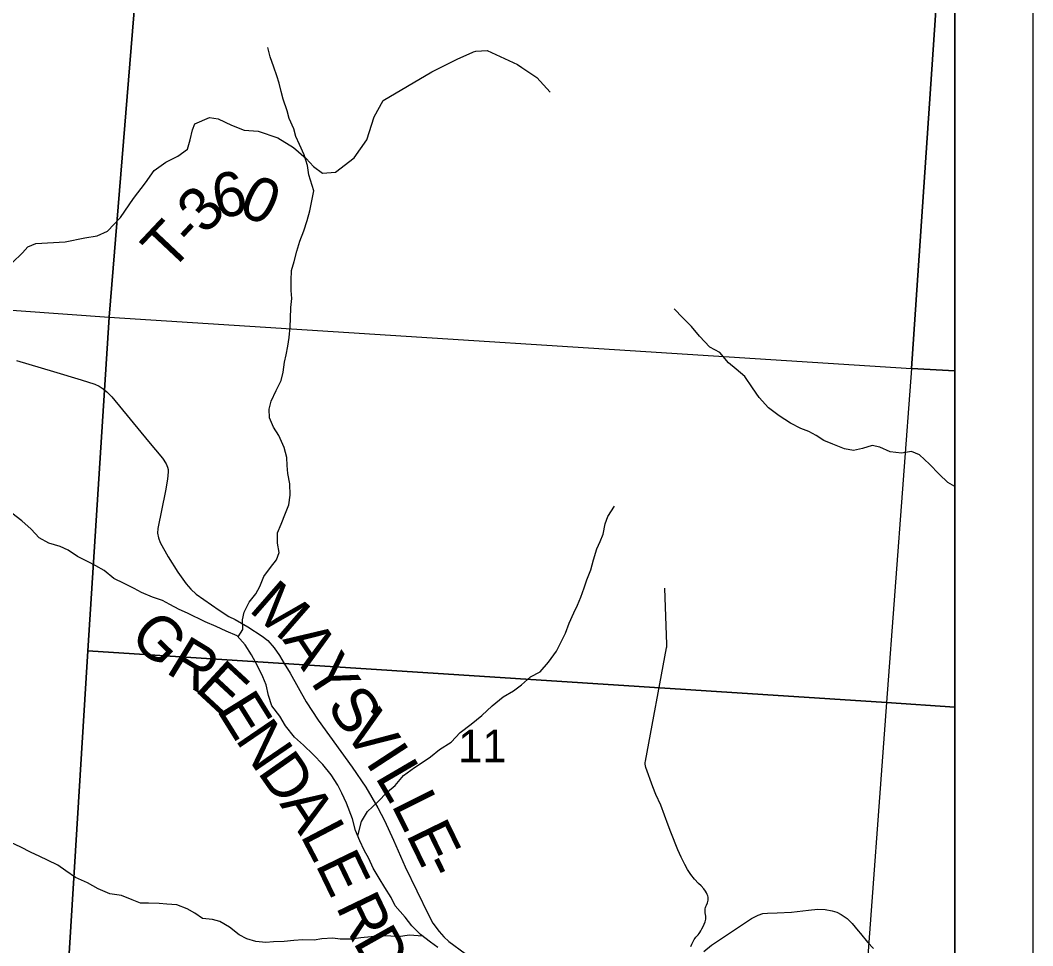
# Model space of a CAD drawing. Extents: x 39.8 to 73.8, y 13 to 35.
# Drawn here: x 47.463 to 48.763, y 32.203 to 33.391 of the extents above; entities that cross this region are included whole.
import ezdxf

# ---------------------------------------------------------------- set-up
doc = ezdxf.new("R2010")
doc.units = 0
for name, color, linetype in [('GM_X_Corporation', 7, 'Continuous'), ('GM_X_Minor_River', 7, 'Continuous'), ('GM_X_Section_Text', 7, 'Continuous'), ('GM_X_Township_Road', 7, 'Continuous'), ('GM_X_Township_Road_Text', 7, 'Continuous'), ('SH_Data', 7, 'Continuous')]:
    doc.layers.add(name, color=color, linetype=linetype)

msp = doc.modelspace()

# ---------------------------------------------------------------- linework, layer by layer
at = {"layer": 'GM_X_Corporation'}
msp.add_lwpolyline([(47.095, 27.8783), (47.5149, 27.8498), (47.5414, 27.8484), (48.663, 27.7809), (48.663, 33.865), (43.6158, 33.865)], dxfattribs=at)
for points in [[(47.647, 33.865), (46.6307, 33.865), (46.5718, 33.0824), (47.5774, 33.0099)], [(48.663, 33.7628), (48.663, 33.865), (47.647, 33.865), (47.5774, 33.0099), (48.6073, 32.9443)], [(48.663, 32.941), (48.663, 33.7628), (48.6073, 32.9443)], [(47.5774, 33.0099), (47.5501, 32.582), (47.5261, 32.1933), (47.514, 31.9975), (46.4973, 32.0662), (46.5718, 33.0824)], [(47.5774, 33.0099), (48.6073, 32.9443), (48.5754, 32.5153), (47.5501, 32.582)], [(48.663, 32.5097), (48.663, 32.941), (48.6073, 32.9443), (48.5754, 32.5153)], [(47.5501, 32.582), (48.5754, 32.5153), (48.5476, 32.1383), (47.5261, 32.1933)], [(48.663, 32.1321), (48.663, 32.5097), (48.5754, 32.5153), (48.5476, 32.1383)]]:
    msp.add_lwpolyline(points, close=True, dxfattribs=at)
at = {"layer": 'GM_X_Minor_River'}
for p, q in [((47.784, 33.344), (47.7813, 33.3561)), ((47.789, 33.3307), (47.784, 33.344)), ((47.7925, 33.3197), (47.789, 33.3307)), ((47.7955, 33.3102), (47.7925, 33.3197)), ((47.7982, 33.2996), (47.7955, 33.3102)), ((47.8009, 33.2898), (47.7982, 33.2996)), ((47.8059, 33.275), (47.8009, 33.2898)), ((47.8086, 33.2648), (47.8059, 33.275)), ((47.8143, 33.2519), (47.8086, 33.2648)), ((47.817, 33.242), (47.8143, 33.2519)), ((47.8216, 33.2314), (47.817, 33.242)), ((47.8277, 33.2185), (47.8216, 33.2314)), ((47.832, 33.2045), (47.8277, 33.2185)), ((47.8339, 33.1928), (47.832, 33.2045)), ((47.84, 33.1723), (47.8339, 33.1928)), ((47.8349, 33.1465), (47.84, 33.1723)), ((47.8315, 33.134), (47.8349, 33.1465)), ((47.8274, 33.121), (47.8315, 33.134)), ((47.8221, 33.1077), (47.8274, 33.121)), ((47.8184, 33.0948), (47.8221, 33.1077)), ((47.8151, 33.0815), (47.8184, 33.0948)), ((47.8117, 33.0698), (47.8151, 33.0815)), ((47.811, 33.0569), (47.8117, 33.0698)), ((47.8111, 33.0444), (47.811, 33.0569)), ((47.8119, 33.0341), (47.8111, 33.0444)), ((47.8108, 33.0224), (47.8119, 33.0341)), ((47.8101, 33.0083), (47.8108, 33.0224)), ((48.3137, 33.0092), (48.3027, 33.0209)), ((47.8097, 32.9977), (47.8101, 33.0083)), ((48.3251, 32.9982), (48.3137, 33.0092)), ((47.8083, 32.984), (47.8097, 32.9977)), ((48.3354, 32.9857), (48.3251, 32.9982)), ((48.3483, 32.9717), (48.3354, 32.9857)), ((47.8068, 32.9727), (47.8083, 32.984)), ((47.8027, 32.9522), (47.8046, 32.9616)), ((47.8046, 32.9616), (47.8068, 32.9727)), ((48.3612, 32.9645), (48.3483, 32.9717)), ((48.3726, 32.9513), (48.3612, 32.9645)), ((47.8009, 32.9393), (47.8027, 32.9522)), ((48.3821, 32.9434), (48.3726, 32.9513)), ((47.7983, 32.9286), (47.8009, 32.9393)), ((48.3932, 32.9339), (48.3821, 32.9434)), ((48.4031, 32.9195), (48.3932, 32.9339)), ((47.7919, 32.9157), (47.7983, 32.9286)), ((47.7855, 32.902), (47.7919, 32.9157)), ((48.4118, 32.9067), (48.4031, 32.9195)), ((47.7829, 32.8918), (47.7855, 32.902)), ((48.4236, 32.8938), (48.4118, 32.9067)), ((47.7834, 32.8808), (47.7829, 32.8918)), ((48.4373, 32.8832), (48.4236, 32.8938)), ((48.4521, 32.8738), (48.4373, 32.8832)), ((47.7883, 32.869), (47.7834, 32.8808)), ((47.7952, 32.8581), (47.7883, 32.869)), ((48.4654, 32.867), (48.4521, 32.8738)), ((47.8021, 32.8429), (47.7952, 32.8581)), ((48.4756, 32.8632), (48.4654, 32.867)), ((48.4851, 32.8583), (48.4756, 32.8632)), ((48.495, 32.8519), (48.4851, 32.8583)), ((47.8055, 32.83), (47.8021, 32.8429)), ((48.5064, 32.847), (48.495, 32.8519)), ((48.5212, 32.841), (48.5064, 32.847)), ((48.5567, 32.8453), (48.5446, 32.8415)), ((48.5666, 32.843), (48.5567, 32.8453)), ((48.5799, 32.837), (48.5666, 32.843)), ((47.806, 32.8198), (47.8055, 32.83)), ((48.5329, 32.8388), (48.5212, 32.841)), ((48.5446, 32.8415), (48.5329, 32.8388)), ((48.5943, 32.8355), (48.5799, 32.837)), ((48.6075, 32.8375), (48.5943, 32.8355)), ((48.6178, 32.8333), (48.6075, 32.8375)), ((48.6303, 32.8212), (48.6178, 32.8333)), ((47.8068, 32.8092), (47.806, 32.8198)), ((48.6429, 32.8084), (48.6303, 32.8212)), ((47.8095, 32.7959), (47.8068, 32.8092)), ((48.6539, 32.7978), (48.6429, 32.8084)), ((47.8099, 32.7815), (47.8095, 32.7959)), ((48.663, 32.7928), (48.6539, 32.7978)), ((47.8081, 32.7693), (47.8099, 32.7815)), ((47.804, 32.7583), (47.8081, 32.7693)), ((48.2175, 32.7543), (48.2261, 32.7676)), ((47.7983, 32.7443), (47.804, 32.7583)), ((48.2141, 32.7448), (48.2175, 32.7543)), ((47.7935, 32.7332), (47.7983, 32.7443)), ((48.2115, 32.7315), (48.2141, 32.7448)), ((47.7935, 32.72), (47.7935, 32.7332)), ((48.2078, 32.722), (48.2115, 32.7315)), ((47.7955, 32.7082), (47.7935, 32.72)), ((48.2036, 32.7125), (48.2078, 32.722)), ((47.7921, 32.6987), (47.7955, 32.7082)), ((48.1992, 32.6985), (48.2036, 32.7125)), ((47.7759, 32.6774), (47.7846, 32.6888)), ((47.7846, 32.6888), (47.7921, 32.6987)), ((48.1958, 32.6856), (48.1992, 32.6985)), ((47.7707, 32.6645), (47.7759, 32.6774)), ((48.1906, 32.6727), (48.1958, 32.6856)), ((47.7658, 32.655), (47.7707, 32.6645)), ((48.1827, 32.6506), (48.1872, 32.6628)), ((48.1872, 32.6628), (48.1906, 32.6727)), ((47.7571, 32.6444), (47.7658, 32.655)), ((48.1786, 32.6404), (48.1827, 32.6506)), ((47.7507, 32.6314), (47.7571, 32.6444)), ((48.1737, 32.6305), (48.1786, 32.6404)), ((47.7485, 32.6216), (47.7507, 32.6314)), ((48.1681, 32.6172), (48.1737, 32.6305)), ((47.7431, 32.5996), (47.7489, 32.6091)), ((47.7489, 32.6091), (47.7485, 32.6216)), ((48.1632, 32.6043), (48.1681, 32.6172)), ((48.158, 32.5944), (48.1632, 32.6043)), ((48.1516, 32.5815), (48.158, 32.5944)), ((48.1414, 32.5671), (48.1516, 32.5815)), ((48.1305, 32.5549), (48.1414, 32.5671)), ((48.1067, 32.5381), (48.1184, 32.5484)), ((48.1184, 32.5484), (48.1305, 32.5549)), ((48.0965, 32.5305), (48.1067, 32.5381)), ((48.069, 32.5114), (48.0833, 32.5229)), ((48.0833, 32.5229), (48.0965, 32.5305)), ((48.0558, 32.4989), (48.069, 32.5114)), ((48.0422, 32.4875), (48.0558, 32.4989)), ((48.0282, 32.4768), (48.0422, 32.4875)), ((48.0165, 32.4646), (48.0282, 32.4768)), ((47.9901, 32.4456), (48.0014, 32.4551)), ((48.0014, 32.4551), (48.0165, 32.4646)), ((47.9791, 32.4387), (47.9901, 32.4456)), ((47.9554, 32.4216), (47.9693, 32.4322)), ((47.9693, 32.4322), (47.9791, 32.4387)), ((47.9444, 32.409), (47.9554, 32.4216)), ((47.9218, 32.3877), (47.9346, 32.401)), ((47.9346, 32.401), (47.9444, 32.409)), ((47.9015, 32.3626), (47.909, 32.3755)), ((47.909, 32.3755), (47.9218, 32.3877)), ((47.8965, 32.3443), (47.9015, 32.3626)), ((47.4639, 32.3297), (47.4513, 32.3357)), ((47.4764, 32.3233), (47.4639, 32.3297)), ((47.4885, 32.3177), (47.4764, 32.3233)), ((47.4984, 32.3131), (47.4885, 32.3177)), ((47.5117, 32.3067), (47.4984, 32.3131)), ((47.5219, 32.2996), (47.5117, 32.3067)), ((47.5341, 32.2909), (47.5219, 32.2996)), ((47.5496, 32.2841), (47.5341, 32.2909)), ((47.5633, 32.2762), (47.5496, 32.2841)), ((47.5781, 32.2701), (47.5633, 32.2762)), ((47.5933, 32.2679), (47.5781, 32.2701)), ((47.6069, 32.2623), (47.5933, 32.2679)), ((47.6175, 32.2581), (47.6069, 32.2623)), ((47.6278, 32.2578), (47.6175, 32.2581)), ((47.6418, 32.2574), (47.6278, 32.2578)), ((47.6516, 32.2567), (47.6418, 32.2574)), ((47.6641, 32.256), (47.6516, 32.2567)), ((47.6774, 32.2507), (47.6641, 32.256)), ((47.6873, 32.2451), (47.6774, 32.2507)), ((47.6971, 32.2383), (47.6873, 32.2451)), ((47.71, 32.2368), (47.6971, 32.2383)), ((47.7195, 32.2346), (47.71, 32.2368)), ((47.732, 32.227), (47.7195, 32.2346)), ((47.7442, 32.2172), (47.732, 32.227)), ((47.754, 32.2123), (47.7442, 32.2172)), ((47.7658, 32.2089), (47.754, 32.2123)), ((47.7787, 32.2074), (47.7658, 32.2089)), ((47.7885, 32.2082), (47.7787, 32.2074)), ((47.8022, 32.2086), (47.7885, 32.2082)), ((47.8146, 32.2102), (47.8022, 32.2086)), ((47.826, 32.211), (47.8146, 32.2102)), ((47.8404, 32.2107), (47.826, 32.211)), ((47.8506, 32.2122), (47.8404, 32.2107)), ((47.8646, 32.213), (47.8506, 32.2122)), ((47.8741, 32.2119), (47.8646, 32.213)), ((47.8885, 32.2116), (47.8741, 32.2119)), ((47.9006, 32.2135), (47.8885, 32.2116)), ((47.9138, 32.2147), (47.9006, 32.2135)), ((47.9263, 32.2159), (47.9138, 32.2147)), ((47.9392, 32.2155), (47.9263, 32.2159)), ((47.9487, 32.2148), (47.9392, 32.2155)), ((47.9627, 32.2171), (47.9487, 32.2148)), ((47.9802, 32.2156), (47.9627, 32.2171))]:
    msp.add_line(p, q, dxfattribs=at)
for points in [[(47.4655, 32.7485), (47.4526, 32.7583)], [(47.9995, 32.2009), (47.99, 32.2081), (47.9771, 32.2179), (47.966, 32.2289), (47.9573, 32.2402), (47.9447, 32.2546), (47.9394, 32.2652), (47.9314, 32.2781), (47.9241, 32.2902), (47.9165, 32.3031), (47.9108, 32.3152), (47.9046, 32.3258), (47.8993, 32.3379), (47.8936, 32.3512), (47.8897, 32.3663), (47.882, 32.3861), (47.8763, 32.3993), (47.871, 32.4095), (47.8622, 32.4228), (47.8519, 32.436), (47.8394, 32.4489), (47.8268, 32.4606), (47.8154, 32.4712), (47.8036, 32.4856), (47.7964, 32.4981), (47.7861, 32.5113), (47.7819, 32.5246), (47.7788, 32.5382), (47.7746, 32.5484), (47.7677, 32.5625), (47.7601, 32.5765), (47.752, 32.5897), (47.7418, 32.6011), (47.7277, 32.6071), (47.7148, 32.6131), (47.7008, 32.6188), (47.678, 32.6301), (47.6674, 32.635), (47.6553, 32.6414), (47.6458, 32.6463), (47.6329, 32.6508), (47.6188, 32.6568), (47.6094, 32.6617), (47.5968, 32.6681), (47.5836, 32.6745), (47.571, 32.6851), (47.5604, 32.6908), (47.5505, 32.6961), (47.5369, 32.7028), (47.5247, 32.7111), (47.5145, 32.7157), (47.5, 32.7198), (47.4875, 32.7266), (47.4773, 32.7379), (47.4655, 32.7485)]]:
    msp.add_lwpolyline(points, dxfattribs=at)
at = {"layer": 'GM_X_Township_Road'}
for points in [[(47.4529, 33.0796), (47.4664, 33.0924), (47.4731, 33.1001), (47.4833, 33.1044), (47.5208, 33.1068), (47.5462, 33.1116), (47.5621, 33.1145), (47.5753, 33.1204), (47.5921, 33.1381), (47.6088, 33.1622), (47.6241, 33.1826), (47.6353, 33.1983), (47.6503, 33.2091), (47.6658, 33.2166), (47.6782, 33.2255), (47.6814, 33.2377), (47.6846, 33.2506), (47.6876, 33.2583), (47.7061, 33.2661), (47.7175, 33.2647), (47.7343, 33.2566), (47.7507, 33.25), (47.7686, 33.2487), (47.7941, 33.2403), (47.814, 33.2276), (47.8305, 33.2138), (47.8398, 33.2032), (47.8513, 33.195), (47.868, 33.196), (47.892, 33.2146), (47.908, 33.2376), (47.9178, 33.2673), (47.9293, 33.288), (47.9918, 33.3249), (48.0242, 33.3413), (48.0443, 33.3499), (48.0452, 33.3503)], [(48.0452, 33.3503), (48.048, 33.3515), (48.0627, 33.3524), (48.1017, 33.3343), (48.1073, 33.3305)], [(48.1073, 33.3305), (48.1262, 33.3175), (48.1436, 33.2987)], [(47.4587, 32.9543), (47.5059, 32.9402), (47.5415, 32.9295), (47.5592, 32.924), (47.5648, 32.9215), (47.5699, 32.9182), (47.5745, 32.9143), (47.5765, 32.9122), (47.5808, 32.9076), (47.6281, 32.8504), (47.646, 32.8291), (47.6508, 32.8217), (47.6524, 32.8175), (47.653, 32.8145), (47.6532, 32.8114), (47.6525, 32.8022), (47.6497, 32.7871), (47.6397, 32.7388), (47.6395, 32.7327), (47.6407, 32.7266), (47.6429, 32.7209), (47.6533, 32.7024), (47.6655, 32.6826), (47.6762, 32.6677), (47.6822, 32.6609), (47.6891, 32.6547), (47.7185, 32.6339), (47.7311, 32.626), (47.7393, 32.6219), (47.7554, 32.6126), (47.7739, 32.6006), (47.7811, 32.5951), (47.7893, 32.5855), (47.796, 32.576), (47.8022, 32.5654), (47.8099, 32.5533), (47.8199, 32.5348), (47.8305, 32.5163), (47.8458, 32.4929), (47.8893, 32.4324), (47.9067, 32.4067), (47.9224, 32.3805), (47.9309, 32.3642), (47.9424, 32.3387), (47.9574, 32.3047), (47.9872, 32.2432), (47.993, 32.2325), (48.001, 32.2216), (48.0069, 32.2148), (48.0135, 32.2089), (48.0346, 32.1933)], [(48.3243, 32.2022), (48.3255, 32.2054), (48.3265, 32.2078), (48.3274, 32.2098), (48.3284, 32.2115), (48.3295, 32.213), (48.3307, 32.2144), (48.3318, 32.2158), (48.3333, 32.2174), (48.3346, 32.219), (48.3358, 32.2205), (48.337, 32.2224), (48.3384, 32.225), (48.3399, 32.2281), (48.3413, 32.2311), (48.3424, 32.2339), (48.343, 32.2359), (48.3433, 32.2376), (48.3434, 32.239), (48.3433, 32.2414), (48.343, 32.2435), (48.3426, 32.2454), (48.3424, 32.2475), (48.3424, 32.2492), (48.3426, 32.2507), (48.343, 32.2523), (48.3434, 32.2536), (48.344, 32.2552), (48.3453, 32.2584), (48.3458, 32.2601), (48.3463, 32.2618), (48.3464, 32.2637), (48.3463, 32.2657), (48.3459, 32.2674), (48.3452, 32.2692), (48.3443, 32.2712), (48.343, 32.2735), (48.3408, 32.2765), (48.3372, 32.2803), (48.3341, 32.2834), (48.3286, 32.2889), (48.324, 32.2947), (48.3197, 32.3012), (48.3162, 32.3074), (48.3115, 32.3172), (48.3073, 32.3266), (48.2985, 32.349), (48.2951, 32.3581), (48.2855, 32.3837), (48.2792, 32.3975), (48.2755, 32.4071), (48.2662, 32.4322), (48.2657, 32.4343), (48.2655, 32.4363), (48.2655, 32.4384), (48.2657, 32.4403), (48.293, 32.5858), (48.2931, 32.5868), (48.2932, 32.5879), (48.2933, 32.5889), (48.2933, 32.59), (48.2907, 32.6622)], [(48.3409, 32.196), (48.3505, 32.2039), (48.3814, 32.2247), (48.4021, 32.2385), (48.4104, 32.2426), (48.4163, 32.2445), (48.4224, 32.2453), (48.4348, 32.2457), (48.4534, 32.2465), (48.475, 32.249), (48.4873, 32.2501), (48.4965, 32.2498), (48.5057, 32.2483), (48.5116, 32.2463), (48.5171, 32.2435), (48.5248, 32.2383), (48.5312, 32.2319), (48.539, 32.2223), (48.5418, 32.2189), (48.5508, 32.2078), (48.5587, 32.1998)]]:
    msp.add_lwpolyline(points, dxfattribs=at)
at = {"layer": 'SH_Data'}
for p, q in [((48.763, 33.965), (48.763, 26.965)), ((48.663, 33.865), (48.663, 27.065))]:
    msp.add_line(p, q, dxfattribs=at)

# ---------------------------------------------------------------- texts
at = {"layer": 'GM_X_Section_Text'}
msp.add_text('11', height=0.04186, rotation=0, dxfattribs=at).set_placement((48.0253, 32.4387))
at = {"layer": 'GM_X_Township_Road_Text'}
for s, rotation, p in [('6', 12.6235, (47.7168, 33.1353)), ('0', 334.8222, (47.741, 33.144)), ('3', 46.9796, (47.7008, 33.1144)), ('T', 46.7387, (47.6557, 33.0664)), ('-', 46.843, (47.6849, 33.0974)), ('M', 318.923, (47.7553, 32.6336)), ('G', 315.4662, (47.6015, 32.5983)), ('A', 303.8537, (47.7992, 32.5961)), ('R', 328.6115, (47.6484, 32.5545)), ('Y', 302.997, (47.8269, 32.5547)), ('E', 317.1673, (47.6858, 32.532)), ('E', 301.9686, (47.7145, 32.5062)), ('S', 305.0198, (47.8554, 32.511)), ('V', 304.7894, (47.8773, 32.4796)), ('N', 304.3224, (47.7384, 32.468)), ('D', 305.0841, (47.767, 32.426)), ('I', 303.0969, (47.9056, 32.4389)), ('L', 300.3243, (47.918, 32.42)), ('L', 296.6091, (47.939, 32.3842)), ('A', 303.2678, (47.7955, 32.3855)), ('L', 297.6576, (47.8222, 32.3449)), ('E', 295.9498, (47.9579, 32.3463)), ('E', 295.7965, (47.8417, 32.3077)), ('-', 295.9531, (47.9765, 32.3081)), ('R', 295.6853, (47.8678, 32.2536)), ('D', 299.2689, (47.8898, 32.2081))]:
    msp.add_text(s, height=0.0568, rotation=rotation, dxfattribs=at).set_placement(p)

doc.saveas('drawing.dxf')
